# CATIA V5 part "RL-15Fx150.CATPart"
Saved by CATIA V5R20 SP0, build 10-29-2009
Part number: _RL-15Fx150
Definition: NONE
Nomenclature: _RL-15Fx150
Source: Unknown
Description: PART-_RL-15Fx150-DESC
Bounding box of the stored display mesh (mm): x -150 to 14, y -8.5 to 8.5, z -8.5 to 8.5
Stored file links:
  C:\Users\Utente\Desktop\IO LAVORO\3D X SITO CF\X SITO\PLASTICA\RLF\RL-15Fx150.CATPart
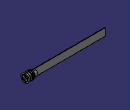
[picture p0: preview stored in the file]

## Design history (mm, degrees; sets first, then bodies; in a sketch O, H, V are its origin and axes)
Body1 "_RL-15Fx150" (main body)
  Solid1: solid without history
